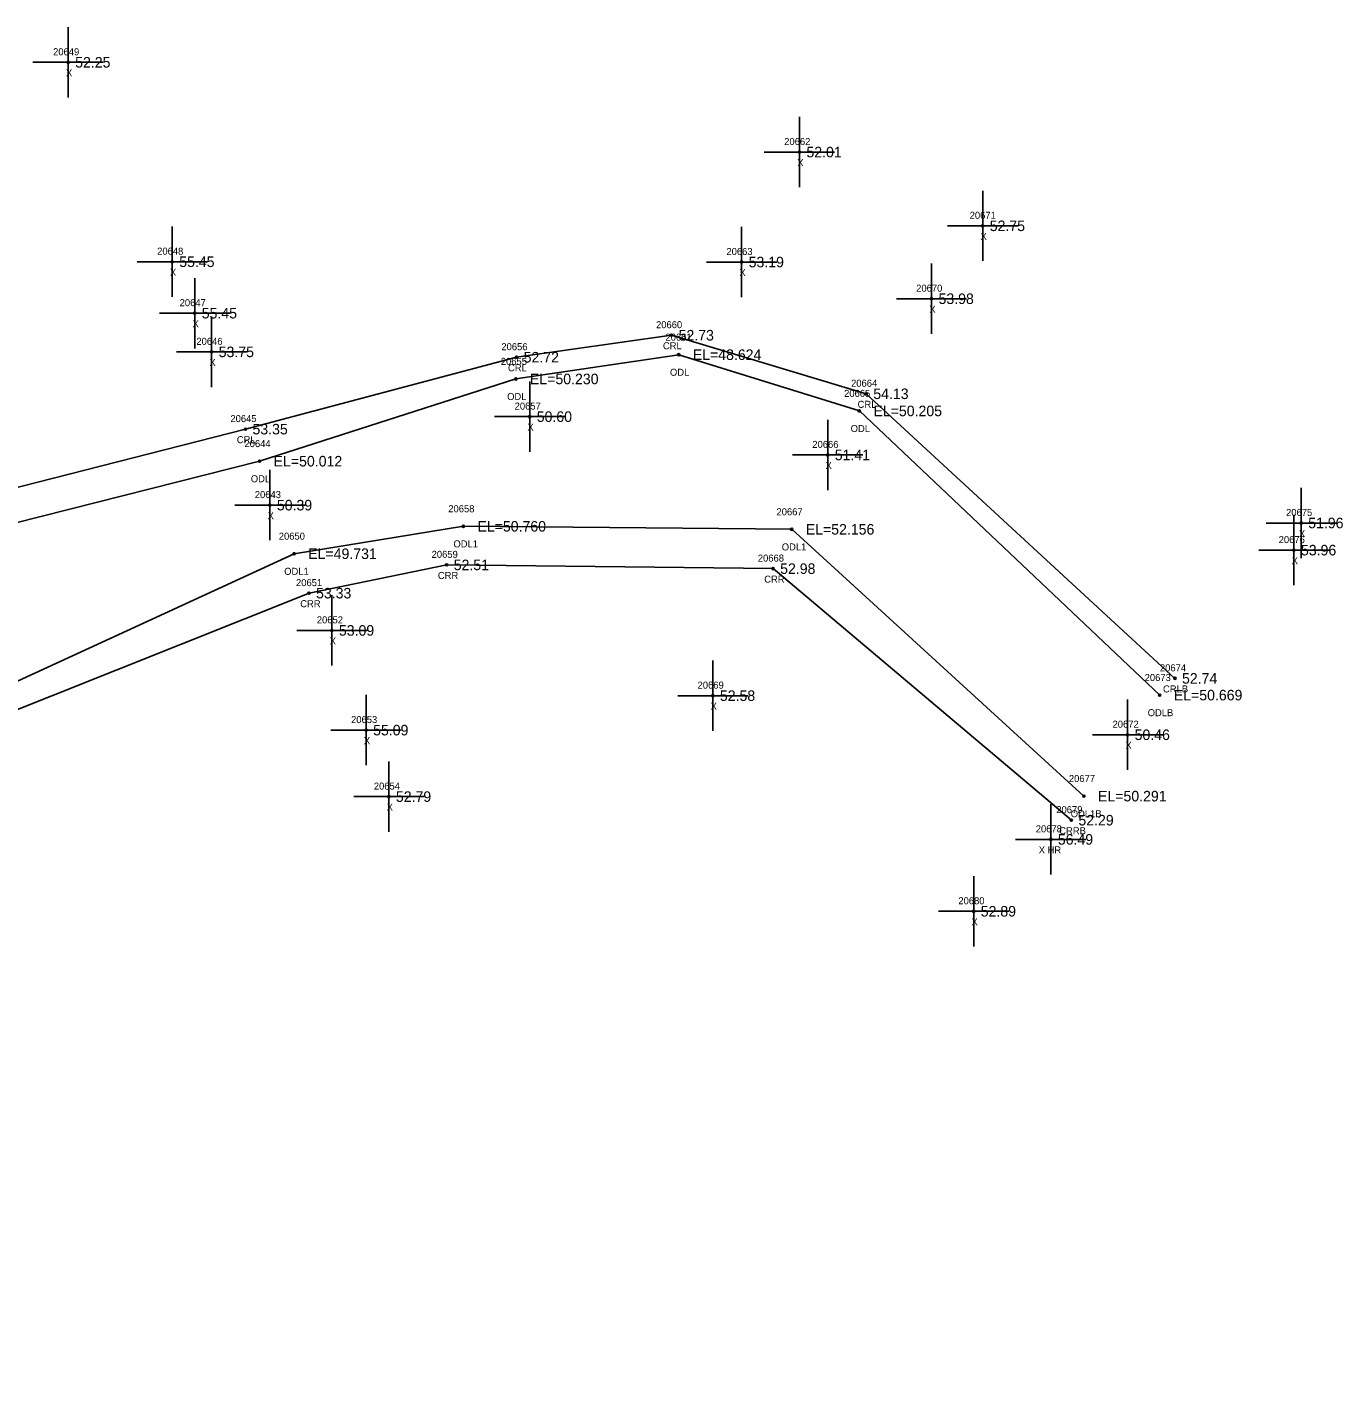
# Model space of a CAD drawing. Extents: x 2396547 to 2397655, y 770185 to 772649.
# Drawn here: x 2397377.8 to 2397565, y 771400.3 to 771593.4 of the extents above; entities that cross this region are included whole.
import ezdxf

# ---------------------------------------------------------------- set-up
doc = ezdxf.new("R2010")
doc.units = 0
for name, color, linetype in [('RD_EX_H2O', 7, 'Continuous'), ('RD_EX_H2O_txCode', 7, 'Continuous'), ('RD_EX_Misc', 7, 'Continuous'), ('RD_EX_Misc_txCode', 7, 'Continuous'), ('RD_EX_TX_H2O_ELEV', 7, 'Continuous'), ('RD_EX_TX_Misc_ELEV', 7, 'Continuous'), ('RD_SMD_Locator', 7, 'Continuous')]:
    doc.layers.add(name, color=color, linetype=linetype)

msp = doc.modelspace()

# ---------------------------------------------------------------- linework, layer by layer
at = {"layer": 'RD_EX_H2O'}
for points in [[(2397026.41, 771393.39), (2397070.16, 771405.14), (2397085.18, 771412.94), (2397115.64, 771424.52), (2397174.69, 771450.34), (2397230.25, 771466.48), (2397283.24, 771491.48), (2397342.91, 771519.42), (2397408.89, 771536.24), (2397447.46, 771546.47), (2397469.5, 771549.6), (2397497.19, 771541.27), (2397541.1, 771500.79)], [(2397042.3, 771381.6), (2397067.83, 771395.64), (2397118.36, 771417.53), (2397176.74, 771444.94), (2397209.62, 771454.54), (2397231.6, 771461.44), (2397284.94, 771486.86), (2397344.87, 771514.98), (2397410.89, 771531.68), (2397447.35, 771543.38), (2397470.51, 771546.83), (2397496.21, 771538.83), (2397538.93, 771498.41)], [(2397029.25, 771363), (2397046.94, 771364.51), (2397071.53, 771381.48), (2397124.8, 771403.82), (2397183.53, 771425.21), (2397238.71, 771441.76), (2397294.15, 771464.26), (2397352.71, 771489.51), (2397415.81, 771518.52), (2397439.88, 771522.42), (2397486.58, 771521.99), (2397528.15, 771484.04)], [(2397041.52, 771355.95), (2397076.78, 771367.04), (2397074.45, 771374.78), (2397101.55, 771387.62), (2397127, 771397.33), (2397184.13, 771422.52), (2397239.58, 771440.33), (2397295.12, 771461.42), (2397353.86, 771487.36), (2397417.93, 771512.91), (2397437.51, 771516.93), (2397483.94, 771516.4), (2397526.36, 771480.62)]]:
    msp.add_lwpolyline(points, dxfattribs=at)
at = {"layer": 'RD_EX_Misc'}
for p, q in [((2397383.67, 771583.42), (2397383.67, 771593.42)), ((2397378.67, 771588.42), (2397388.67, 771588.42)), ((2397487.68, 771570.65), (2397487.68, 771580.65)), ((2397482.68, 771575.65), (2397492.68, 771575.65)), ((2397513.75, 771560.16), (2397513.75, 771570.16)), ((2397398.47, 771555.05), (2397398.47, 771565.05)), ((2397479.46, 771555.01), (2397479.46, 771565.01)), ((2397508.75, 771565.16), (2397518.75, 771565.16)), ((2397393.47, 771560.05), (2397403.47, 771560.05)), ((2397474.46, 771560.01), (2397484.46, 771560.01)), ((2397506.47, 771549.79), (2397506.47, 771559.79)), ((2397401.67, 771547.73), (2397401.67, 771557.73)), ((2397501.47, 771554.79), (2397511.47, 771554.79)), ((2397396.67, 771552.73), (2397406.67, 771552.73)), ((2397404.08, 771542.23), (2397404.08, 771552.23)), ((2397399.08, 771547.23), (2397409.08, 771547.23)), ((2397449.32, 771533.02), (2397449.32, 771543.02)), ((2397444.32, 771538.02), (2397454.32, 771538.02)), ((2397491.71, 771527.57), (2397491.71, 771537.57)), ((2397486.71, 771532.57), (2397496.71, 771532.57)), ((2397412.36, 771520.43), (2397412.36, 771530.43)), ((2397559.05, 771517.89), (2397559.05, 771527.89)), ((2397407.36, 771525.43), (2397417.36, 771525.43)), ((2397558.02, 771514.03), (2397558.02, 771524.03)), ((2397554.05, 771522.89), (2397564.05, 771522.89)), ((2397553.02, 771519.03), (2397563.02, 771519.03)), ((2397421.18, 771502.61), (2397421.18, 771512.61)), ((2397416.18, 771507.61), (2397426.18, 771507.61)), ((2397475.37, 771493.33), (2397475.37, 771503.33)), ((2397426.05, 771488.43), (2397426.05, 771498.43)), ((2397470.37, 771498.33), (2397480.37, 771498.33)), ((2397534.36, 771487.77), (2397534.36, 771497.77)), ((2397421.05, 771493.43), (2397431.05, 771493.43)), ((2397529.36, 771492.77), (2397539.36, 771492.77)), ((2397429.29, 771478.97), (2397429.29, 771488.97)), ((2397424.29, 771483.97), (2397434.29, 771483.97)), ((2397523.44, 771472.89), (2397523.44, 771482.89)), ((2397518.44, 771477.89), (2397528.44, 771477.89)), ((2397512.47, 771462.66), (2397512.47, 771472.66)), ((2397507.47, 771467.66), (2397517.47, 771467.66))]:
    msp.add_line(p, q, dxfattribs=at)
at = {"layer": 'RD_SMD_Locator'}
for centre in [(2397383.67, 771588.42), (2397487.68, 771575.65), (2397513.75, 771565.16), (2397398.47, 771560.05), (2397479.46, 771560.01), (2397506.47, 771554.79), (2397401.67, 771552.73), (2397469.5, 771549.6), (2397404.08, 771547.23), (2397470.51, 771546.83), (2397447.46, 771546.47), (2397447.35, 771543.38), (2397497.19, 771541.27), (2397496.21, 771538.83), (2397449.32, 771538.02), (2397408.89, 771536.24), (2397410.89, 771531.68), (2397491.71, 771532.57), (2397412.36, 771525.43), (2397439.88, 771522.42), (2397486.58, 771521.99), (2397559.05, 771522.89), (2397415.81, 771518.52), (2397558.02, 771519.03), (2397437.51, 771516.93), (2397483.94, 771516.4), (2397417.93, 771512.91), (2397421.18, 771507.61), (2397541.1, 771500.79), (2397475.37, 771498.33), (2397538.93, 771498.41), (2397426.05, 771493.43), (2397534.36, 771492.77), (2397429.29, 771483.97), (2397528.15, 771484.04), (2397526.36, 771480.62), (2397523.44, 771477.89), (2397512.47, 771467.66)]:
    msp.add_circle(centre, 0.15, dxfattribs=at)

# ---------------------------------------------------------------- texts
at = {"layer": 'RD_EX_H2O_txCode'}
for s, p in [('20660', (2397467.29, 771550.6)), ('CRL', (2397468.27, 771547.6)), ('20661', (2397468.63, 771548.83)), ('20656', (2397445.29, 771547.47)), ('20655', (2397445.21, 771545.38)), ('CRL', (2397446.23, 771544.47)), ('ODL', (2397469.27, 771543.83)), ('20664', (2397495.03, 771542.27)), ('ODL', (2397446.11, 771540.38)), ('20665', (2397494.04, 771540.83)), ('CRL', (2397495.96, 771539.27)), ('20645', (2397406.75, 771537.24)), ('CRL', (2397407.66, 771534.24)), ('ODL', (2397494.97, 771535.83)), ('20644', (2397408.75, 771533.68)), ('ODL', (2397409.65, 771528.68)), ('20658', (2397437.74, 771524.42)), ('20667', (2397484.42, 771523.99)), ('20650', (2397413.63, 771520.52)), ('ODL1', (2397438.47, 771519.42)), ('ODL1', (2397485.17, 771518.99)), ('20659', (2397435.37, 771517.93)), ('20668', (2397481.77, 771517.4)), ('ODL1', (2397414.4, 771515.52)), ('CRR', (2397436.26, 771514.93)), ('20651', (2397416.08, 771513.91)), ('CRR', (2397482.68, 771514.4)), ('CRR', (2397416.68, 771510.91)), ('20674', (2397538.96, 771501.79)), ('20673', (2397536.79, 771500.41)), ('CRLB', (2397539.4, 771498.79)), ('ODLB', (2397537.22, 771495.41)), ('20677', (2397526.01, 771486.04)), ('20679', (2397524.22, 771481.62)), ('ODL1B', (2397526.27, 771481.04)), ('CRRB', (2397524.64, 771478.62))]:
    msp.add_text(s, height=1, dxfattribs=at).set_placement(p)
at = {"layer": 'RD_EX_Misc_txCode'}
for s, p in [('20649', (2397381.53, 771589.42)), ('X', (2397383.36, 771586.42)), ('20662', (2397485.52, 771576.65)), ('X', (2397487.37, 771573.65)), ('20671', (2397511.9, 771566.16)), ('X', (2397513.44, 771563.16)), ('20648', (2397396.33, 771561.05)), ('20663', (2397477.3, 771561.01)), ('X', (2397398.15, 771558.05)), ('X', (2397479.15, 771558.01)), ('20670', (2397504.29, 771555.79)), ('20647', (2397399.53, 771553.73)), ('X', (2397506.16, 771552.79)), ('X', (2397401.36, 771550.73)), ('20646', (2397401.91, 771548.23)), ('X', (2397403.76, 771545.23)), ('20657', (2397447.18, 771539.02)), ('X', (2397449, 771536.02)), ('20666', (2397489.52, 771533.57)), ('X', (2397491.4, 771530.57)), ('20643', (2397410.22, 771526.43)), ('X', (2397412.04, 771523.43)), ('20675', (2397556.9, 771523.89)), ('X', (2397558.73, 771520.89)), ('20676', (2397555.85, 771520.03)), ('X', (2397557.7, 771517.03)), ('20652', (2397419.04, 771508.61)), ('X', (2397420.87, 771505.61)), ('20669', (2397473.2, 771499.33)), ('X', (2397475.05, 771496.33)), ('20653', (2397423.91, 771494.43)), ('20672', (2397532.22, 771493.77)), ('X', (2397425.73, 771491.43)), ('X', (2397534.05, 771490.77)), ('20654', (2397427.15, 771484.97)), ('X', (2397428.98, 771481.97)), ('20678', (2397521.3, 771478.89)), ('X HR', (2397521.72, 771475.89)), ('20680', (2397510.29, 771468.66)), ('X', (2397512.15, 771465.66))]:
    msp.add_text(s, height=1, dxfattribs=at).set_placement(p)
at = {"layer": 'RD_EX_TX_H2O_ELEV'}
for s, p in [('52.73', (2397470.5, 771548.85)), ('52.72', (2397448.46, 771545.72)), ('EL=48.624', (2397472.51, 771546.08)), ('EL=50.230', (2397449.35, 771542.63)), ('54.13', (2397498.19, 771540.52)), ('EL=50.205', (2397498.21, 771538.08)), ('53.35', (2397409.89, 771535.49)), ('EL=50.012', (2397412.89, 771530.93)), ('EL=50.760', (2397441.88, 771521.67)), ('EL=52.156', (2397488.58, 771521.24)), ('EL=49.731', (2397417.81, 771517.77)), ('52.51', (2397438.51, 771516.18)), ('52.98', (2397484.94, 771515.65)), ('53.33', (2397418.93, 771512.16)), ('52.74', (2397542.1, 771500.04)), ('EL=50.669', (2397540.93, 771497.66)), ('EL=50.291', (2397530.15, 771483.29)), ('52.29', (2397527.36, 771479.87))]:
    msp.add_text(s, height=1.5, dxfattribs=at).set_placement(p)
at = {"layer": 'RD_EX_TX_Misc_ELEV'}
for s, p in [('52.25', (2397384.67, 771587.67)), ('52.01', (2397488.68, 771574.9)), ('52.75', (2397514.75, 771564.41)), ('55.45', (2397399.47, 771559.3)), ('53.19', (2397480.46, 771559.26)), ('53.98', (2397507.47, 771554.04)), ('55.45', (2397402.67, 771551.98)), ('53.75', (2397405.08, 771546.48)), ('50.60', (2397450.32, 771537.27)), ('51.41', (2397492.71, 771531.82)), ('50.39', (2397413.36, 771524.68)), ('51.96', (2397560.05, 771522.14)), ('53.96', (2397559.02, 771518.28)), ('53.09', (2397422.18, 771506.86)), ('52.58', (2397476.37, 771497.58)), ('55.09', (2397427.05, 771492.68)), ('50.46', (2397535.36, 771492.02)), ('52.79', (2397430.29, 771483.22)), ('56.49', (2397524.44, 771477.14)), ('52.89', (2397513.47, 771466.91))]:
    msp.add_text(s, height=1.5, dxfattribs=at).set_placement(p)

doc.saveas('drawing.dxf')
